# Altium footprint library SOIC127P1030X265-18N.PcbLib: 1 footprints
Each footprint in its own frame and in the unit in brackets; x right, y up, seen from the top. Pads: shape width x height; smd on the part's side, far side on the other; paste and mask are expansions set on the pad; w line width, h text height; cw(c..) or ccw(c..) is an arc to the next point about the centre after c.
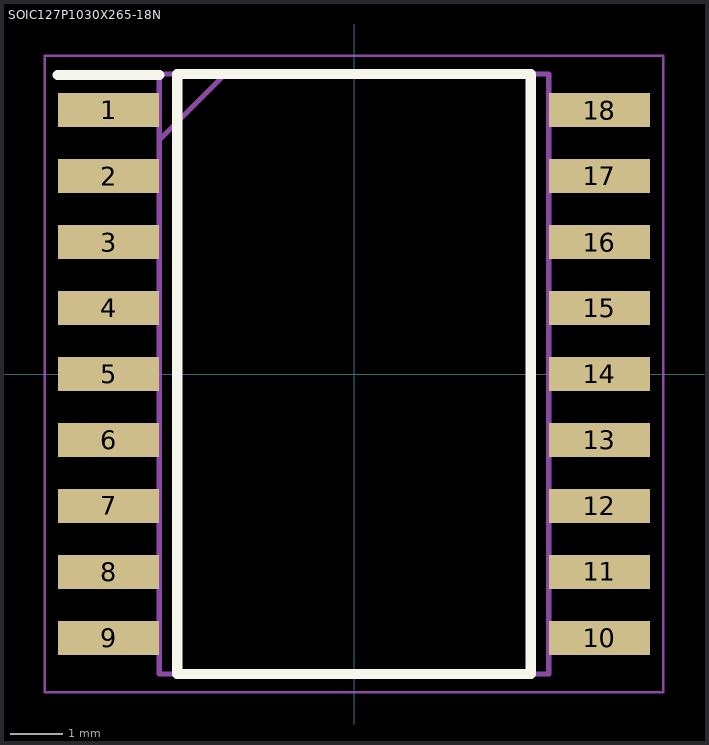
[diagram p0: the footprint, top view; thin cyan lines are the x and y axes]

## SOIC127P1030X265-18N [mm]
pads (18):
  rect 1.95x0.65 smd: 1(-4.725,5.08) 2(-4.725,3.81) 3(-4.725,2.54) 4(-4.725,1.27) 5(-4.725,0) 6(-4.725,-1.27) 7(-4.725,-2.54) 8(-4.725,-3.81) 9(-4.725,-5.08) 10(4.725,-5.08) 11(4.725,-3.81) 12(4.725,-2.54) 13(4.725,-1.27) 14(4.725,0) 15(4.725,1.27) 16(4.725,2.54) 17(4.725,3.81) 18(4.725,5.08)
Top Overlay:
  lines w0.2: -5.7,5.755 -3.75,5.755 ; -3.4,-5.775 3.4,-5.775 3.4,5.775 -3.4,5.775 -3.4,-5.775
Mechanical 15:
  lines w0.1: -3.75,4.505 -2.48,5.775 ; -3.75,-5.775 3.75,-5.775 3.75,5.775 -3.75,5.775 -3.75,-5.775
Mechanical 20:
  lines w0.05: -5.95,-6.125 5.95,-6.125 5.95,6.125 -5.95,6.125 -5.95,-6.125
